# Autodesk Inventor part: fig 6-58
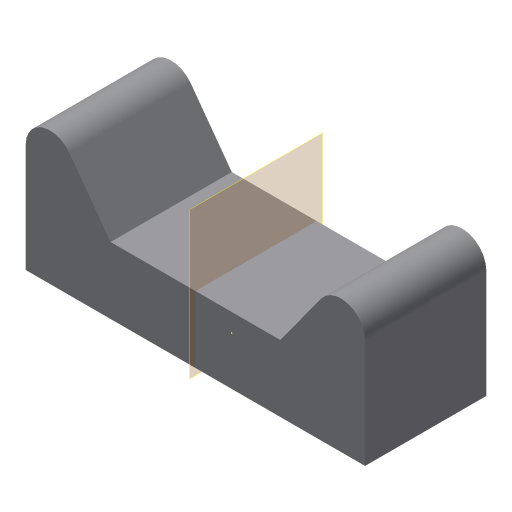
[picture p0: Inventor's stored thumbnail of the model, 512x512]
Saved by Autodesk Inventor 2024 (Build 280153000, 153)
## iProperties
Created: 2011-07
Part Number: fig 6-58
Material: Generic
Document SubType Name: Modeling
Designer: CadCim
Density: 1 g/cm^3
Appearance: Default
Author: CadCim
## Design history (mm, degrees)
sketch "Sketch2"
  geometry: L1 (3, -4)-(17, -4); L2 (17, -4)-(17, 7); L3 (17, 7)-(14, 7); L4 (14, 7)-(10, 1.5); L5 (10, 1.5)-(3, 1.5); L6 (3, -4)-(-11, -4); L7 (-11, -4)-(-11, 7); L8 (-11, 7)-(-8, 7); L9 (-8, 7)-(-4, 1.5); L10 (-4, 1.5)-(3, 1.5); 1 further point
  constraints: 20 end point, 2 parallel, 1 perpendicular
extrude "Extrusion1" new body sketch "Sketch2" distance "d0" = 10; taper "d1" = 0 deg
fillet "Fillet1" dims "d2" = 2
workplane "Work Plane1"
mirror "Mirror1"
body "Solid1"
sketch "Sketch1"
  geometry: 1 further point
